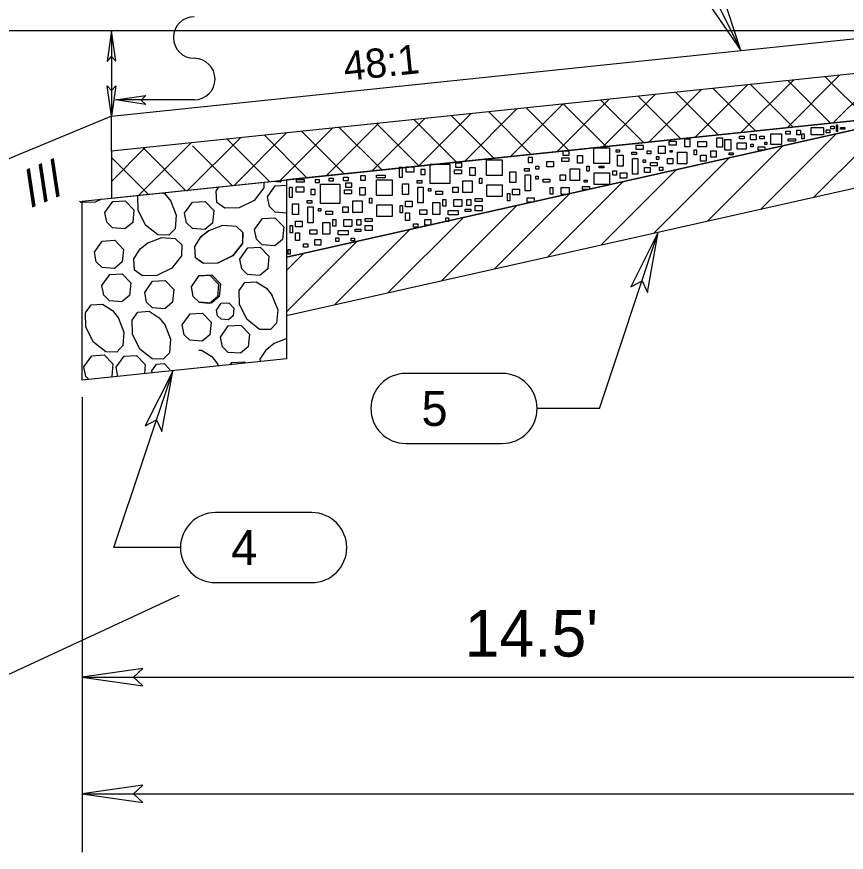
# Model space of a CAD drawing. Extents: x 6561 to 6787, y 19927 to 20919.
# Drawn here: x 6685.44 to 6699.64, y 20854.58 to 20868.89 of the extents above; entities that cross this region are included whole.
import ezdxf

# ---------------------------------------------------------------- set-up
doc = ezdxf.new("R2010")
doc.units = 0
for name, color, linetype in [('Level 1', 7, 'Continuous'), ('Level 10', 7, 'Continuous'), ('Level 3', 7, 'Continuous'), ('Level 4', 7, 'Continuous'), ('Level 5', 7, 'Continuous'), ('Level 7', 7, 'Continuous'), ('Level 8', 7, 'Continuous')]:
    doc.layers.add(name, color=color, linetype=linetype)

msp = doc.modelspace()

# ---------------------------------------------------------------- linework, layer by layer
at = {"layer": 'Level 1'}
for p, q in [((6696.539, 20870.929), (6697.838, 20868.315)), ((6779.047, 20868.65), (6628.473, 20868.65)), ((6687.057, 20868.65), (6687.057, 20867.192)), ((6688.476, 20867.47), (6687.127, 20867.47)), ((6695.417, 20862.184), (6696.424, 20865.206)), ((6687.101, 20859.8), (6688.108, 20862.822)), ((6693.75, 20862.784), (6692.101, 20862.784)), ((6686.557, 20862.377), (6686.557, 20854.582)), ((6695.417, 20862.184), (6694.35, 20862.184)), ((6692.101, 20861.584), (6693.75, 20861.584)), ((6693.75, 20861.584), (6693.75, 20861.584)), ((6690.488, 20860.4), (6688.84, 20860.4)), ((6688.24, 20859.8), (6687.101, 20859.8)), ((6688.84, 20859.2), (6690.488, 20859.2)), ((6690.488, 20859.2), (6690.488, 20859.2)), ((6686.557, 20857.581), (6701.057, 20857.581)), ((6686.557, 20855.581), (6715.557, 20855.581))]:
    msp.add_line(p, q, dxfattribs=at)
for points in [[(6697.838, 20868.315), (6697.514, 20869.313), (6697.45, 20869.103), (6697.245, 20869.18)], [(6687.057, 20868.65), (6686.985, 20868.13), (6687.059, 20868.211), (6687.135, 20868.131)], [(6687.057, 20867.192), (6686.985, 20867.711), (6687.059, 20867.631), (6687.135, 20867.711)], [(6687.127, 20867.47), (6687.647, 20867.542), (6687.566, 20867.467), (6687.646, 20867.392)], [(6696.424, 20865.206), (6695.954, 20864.268), (6696.147, 20864.373), (6696.238, 20864.173)], [(6688.108, 20862.822), (6687.638, 20861.884), (6687.831, 20861.989), (6687.922, 20861.79)], [(6686.557, 20857.581), (6687.596, 20857.432), (6687.436, 20857.581), (6687.596, 20857.731)], [(6686.557, 20855.581), (6687.596, 20855.432), (6687.436, 20855.581), (6687.596, 20855.731)]]:
    msp.add_lwpolyline(points, close=True, dxfattribs=at)
for centre, radius, start, end in [((6688.476, 20868.538), 0.356, 90, 270), ((6688.476, 20867.826), 0.356, 270, 90), ((6692.101, 20862.184), 0.6, 90, 270), ((6693.75, 20862.184), 0.6, 270, 90), ((6688.84, 20859.8), 0.6, 90, 270), ((6690.488, 20859.8), 0.6, 270, 90)]:
    msp.add_arc(centre, radius, start, end, dxfattribs=at)
at = {"layer": 'Level 10'}
for p, q in [((6701.057, 20867.246), (6690.057, 20864.778)), ((6699.091, 20865.805), (6700.381, 20867.094)), ((6698.18, 20865.6), (6699.469, 20866.889)), ((6697.268, 20865.395), (6698.557, 20866.685)), ((6696.356, 20865.191), (6697.646, 20866.48)), ((6695.445, 20864.986), (6696.734, 20866.276)), ((6690.057, 20863.778), (6701.057, 20866.246)), ((6690.057, 20866.1), (6690.057, 20863.033)), ((6694.533, 20864.782), (6695.822, 20866.071)), ((6693.621, 20864.577), (6694.911, 20865.867)), ((6692.71, 20864.373), (6693.999, 20865.662)), ((6691.798, 20864.168), (6693.087, 20865.457)), ((6690.887, 20863.964), (6692.176, 20865.253)), ((6690.057, 20863.841), (6691.264, 20865.048)), ((6690.057, 20864.548), (6690.352, 20864.844)), ((6690.057, 20864.778), (6690.057, 20863.778))]:
    msp.add_line(p, q, dxfattribs=at)
at = {"layer": 'Level 3'}
for p, q in [((6701.057, 20868.05), (6687.057, 20866.592)), ((6699.528, 20867.891), (6698.63, 20866.993)), ((6700.013, 20867.137), (6699.284, 20867.865)), ((6700.318, 20867.973), (6699.42, 20867.075)), ((6697.95, 20867.726), (6697.052, 20866.828)), ((6698.739, 20867.808), (6697.841, 20866.911)), ((6698.732, 20867.003), (6698.004, 20867.732)), ((6699.372, 20867.07), (6698.644, 20867.799)), ((6696.371, 20867.562), (6695.473, 20866.664)), ((6697.16, 20867.644), (6696.262, 20866.746)), ((6697.451, 20866.87), (6696.723, 20867.598)), ((6698.092, 20866.937), (6697.363, 20867.665)), ((6695.582, 20867.48), (6694.684, 20866.582)), ((6696.171, 20866.737), (6695.442, 20867.465)), ((6696.811, 20866.803), (6696.082, 20867.532)), ((6694.003, 20867.315), (6693.105, 20866.417)), ((6694.249, 20866.536), (6693.521, 20867.265)), ((6694.792, 20867.397), (6693.894, 20866.499)), ((6694.89, 20866.603), (6694.161, 20867.332)), ((6695.53, 20866.67), (6694.802, 20867.398)), ((6687.057, 20865.787), (6701.057, 20867.246)), ((6692.424, 20867.151), (6691.526, 20866.253)), ((6692.969, 20866.403), (6692.24, 20867.131)), ((6693.214, 20867.233), (6692.316, 20866.335)), ((6693.609, 20866.47), (6692.88, 20867.198)), ((6690.846, 20866.986), (6689.948, 20866.088)), ((6691.635, 20867.068), (6690.737, 20866.171)), ((6691.688, 20866.27), (6690.959, 20866.998)), ((6692.328, 20866.336), (6691.6, 20867.065)), ((6690.056, 20866.904), (6689.158, 20866.006)), ((6690.407, 20866.136), (6689.678, 20866.865)), ((6691.047, 20866.203), (6690.319, 20866.931)), ((6688.424, 20866.734), (6687.526, 20865.836)), ((6689.267, 20866.822), (6688.352, 20865.907)), ((6689.767, 20866.07), (6689.038, 20866.798)), ((6687.635, 20866.652), (6687.057, 20866.074)), ((6687.057, 20866.592), (6687.057, 20865.787)), ((6688.328, 20865.92), (6687.6, 20866.648)), ((6689.126, 20866.003), (6688.449, 20866.68)), ((6687.688, 20865.853), (6687.057, 20866.484))]:
    msp.add_line(p, q, dxfattribs=at)
at = {"layer": 'Level 4'}
for p, q in [((6701.057, 20867.246), (6690.057, 20866.1)), ((6690.057, 20864.778), (6701.057, 20867.246)), ((6690.057, 20866.1), (6690.057, 20864.778))]:
    msp.add_line(p, q, dxfattribs=at)
for points in [[(6699.252, 20866.869), (6699.04, 20866.869), (6699.04, 20866.994), (6699.252, 20866.994)], [(6699.382, 20867.022), (6699.437, 20867.022), (6699.437, 20866.975), (6699.382, 20866.975)], [(6699.495, 20866.931), (6699.479, 20866.931), (6699.479, 20867.045), (6699.495, 20867.045)], [(6699.547, 20866.998), (6699.617, 20866.998), (6699.617, 20866.971), (6699.547, 20866.971)], [(6697.813, 20866.847), (6697.895, 20866.847), (6697.895, 20866.804), (6697.813, 20866.804)], [(6698.001, 20866.877), (6698.099, 20866.877), (6698.099, 20866.787), (6698.001, 20866.787)], [(6698.237, 20866.802), (6698.166, 20866.802), (6698.166, 20866.85), (6698.237, 20866.85)], [(6698.35, 20866.889), (6698.535, 20866.889), (6698.535, 20866.708), (6698.35, 20866.708)], [(6698.608, 20866.935), (6698.683, 20866.935), (6698.683, 20866.884), (6698.608, 20866.884)], [(6698.797, 20866.951), (6698.859, 20866.951), (6698.859, 20866.869), (6698.797, 20866.869)], [(6698.881, 20866.886), (6698.924, 20866.886), (6698.924, 20866.8), (6698.881, 20866.8)], [(6699.301, 20866.956), (6699.362, 20866.956), (6699.362, 20866.907), (6699.301, 20866.907)], [(6696.732, 20866.695), (6696.61, 20866.695), (6696.61, 20866.761), (6696.732, 20866.761)], [(6696.964, 20866.667), (6696.877, 20866.667), (6696.877, 20866.801), (6696.964, 20866.801)], [(6697.103, 20866.756), (6697.248, 20866.756), (6697.248, 20866.666), (6697.103, 20866.666)], [(6697.429, 20866.819), (6697.527, 20866.819), (6697.527, 20866.658), (6697.429, 20866.658)], [(6697.668, 20866.607), (6697.566, 20866.607), (6697.566, 20866.792), (6697.668, 20866.792)], [(6697.93, 20866.626), (6697.777, 20866.626), (6697.777, 20866.732), (6697.93, 20866.732)], [(6698.009, 20866.714), (6698.048, 20866.714), (6698.048, 20866.666), (6698.009, 20866.666)], [(6698.248, 20866.744), (6698.284, 20866.744), (6698.284, 20866.704), (6698.248, 20866.704)], [(6698.651, 20866.802), (6698.773, 20866.802), (6698.773, 20866.763), (6698.651, 20866.763)], [(6694.9, 20866.593), (6694.79, 20866.593), (6694.79, 20866.522), (6694.9, 20866.522)], [(6695.32, 20866.648), (6695.591, 20866.648), (6695.591, 20866.381), (6695.32, 20866.381)], [(6695.703, 20866.615), (6695.758, 20866.615), (6695.758, 20866.572), (6695.703, 20866.572)], [(6695.97, 20866.577), (6696.053, 20866.577), (6696.053, 20866.534), (6695.97, 20866.534)], [(6696.037, 20866.627), (6696.17, 20866.627), (6696.17, 20866.686), (6696.037, 20866.686)], [(6696.296, 20866.545), (6696.233, 20866.545), (6696.233, 20866.596), (6696.296, 20866.596)], [(6696.429, 20866.678), (6696.543, 20866.678), (6696.543, 20866.552), (6696.429, 20866.552)], [(6696.628, 20866.603), (6696.663, 20866.603), (6696.663, 20866.575), (6696.628, 20866.575)], [(6696.755, 20866.573), (6696.916, 20866.573), (6696.916, 20866.372), (6696.755, 20866.372)], [(6697.038, 20866.616), (6697.081, 20866.616), (6697.081, 20866.53), (6697.038, 20866.53)], [(6697.417, 20866.489), (6697.323, 20866.489), (6697.323, 20866.595), (6697.417, 20866.595)], [(6697.637, 20866.564), (6697.708, 20866.564), (6697.708, 20866.528), (6697.637, 20866.528)], [(6698.249, 20866.611), (6698.135, 20866.611), (6698.135, 20866.666), (6698.249, 20866.666)], [(6693.482, 20866.441), (6693.753, 20866.441), (6693.753, 20866.173), (6693.482, 20866.173)], [(6694.197, 20866.397), (6694.272, 20866.397), (6694.272, 20866.483), (6694.197, 20866.483)], [(6694.517, 20866.415), (6694.631, 20866.415), (6694.631, 20866.325), (6694.517, 20866.325)], [(6694.892, 20866.412), (6694.771, 20866.412), (6694.771, 20866.479), (6694.892, 20866.479)], [(6695.124, 20866.385), (6695.038, 20866.385), (6695.038, 20866.518), (6695.124, 20866.518)], [(6695.825, 20866.337), (6695.723, 20866.337), (6695.723, 20866.522), (6695.825, 20866.522)], [(6695.982, 20866.467), (6696.076, 20866.467), (6696.076, 20866.196), (6695.982, 20866.196)], [(6696.167, 20866.443), (6696.206, 20866.443), (6696.206, 20866.396), (6696.167, 20866.396)], [(6696.386, 20866.454), (6696.437, 20866.454), (6696.437, 20866.497), (6696.386, 20866.497)], [(6696.673, 20866.372), (6696.583, 20866.372), (6696.583, 20866.467), (6696.673, 20866.467)], [(6697.244, 20866.422), (6697.15, 20866.422), (6697.15, 20866.524), (6697.244, 20866.524)], [(6692.045, 20866.311), (6691.986, 20866.311), (6691.986, 20866.146), (6692.045, 20866.146)], [(6692.104, 20866.323), (6692.238, 20866.323), (6692.238, 20866.229), (6692.104, 20866.229)], [(6692.359, 20866.189), (6692.434, 20866.189), (6692.434, 20866.276), (6692.359, 20866.276)], [(6692.52, 20866.37), (6692.854, 20866.37), (6692.854, 20866.036), (6692.52, 20866.036)], [(6693.054, 20866.205), (6692.933, 20866.205), (6692.933, 20866.272), (6693.054, 20866.272)], [(6693.062, 20866.386), (6692.952, 20866.386), (6692.952, 20866.315), (6693.062, 20866.315)], [(6693.286, 20866.177), (6693.199, 20866.177), (6693.199, 20866.311), (6693.286, 20866.311)], [(6694.131, 20866.294), (6694.213, 20866.294), (6694.213, 20866.251), (6694.131, 20866.251)], [(6694.325, 20866.336), (6694.376, 20866.336), (6694.376, 20866.285), (6694.325, 20866.285)], [(6694.916, 20866.291), (6695.077, 20866.291), (6695.077, 20866.09), (6694.916, 20866.09)], [(6695.199, 20866.334), (6695.242, 20866.334), (6695.242, 20866.247), (6695.199, 20866.247)], [(6695.491, 20866.305), (6695.409, 20866.305), (6695.409, 20866.336), (6695.491, 20866.336)], [(6696.186, 20866.309), (6696.284, 20866.309), (6696.284, 20866.226), (6696.186, 20866.226)], [(6696.406, 20866.341), (6696.292, 20866.341), (6696.292, 20866.396), (6696.406, 20866.396)], [(6696.443, 20866.316), (6696.502, 20866.316), (6696.502, 20866.261), (6696.443, 20866.261)], [(6690.785, 20866.126), (6690.856, 20866.126), (6690.856, 20866.079), (6690.785, 20866.079)], [(6691.032, 20866.146), (6691.115, 20866.146), (6691.115, 20866.083), (6691.032, 20866.083)], [(6691.327, 20866.177), (6691.401, 20866.177), (6691.401, 20866.091), (6691.327, 20866.091)], [(6691.598, 20866.181), (6691.747, 20866.181), (6691.747, 20866.134), (6691.598, 20866.134)], [(6693.36, 20866.126), (6693.404, 20866.126), (6693.404, 20866.04), (6693.36, 20866.04)], [(6693.985, 20866.055), (6693.883, 20866.055), (6693.883, 20866.239), (6693.985, 20866.239)], [(6694.142, 20866.184), (6694.237, 20866.184), (6694.237, 20865.913), (6694.142, 20865.913)], [(6694.327, 20866.161), (6694.366, 20866.161), (6694.366, 20866.114), (6694.327, 20866.114)], [(6694.833, 20866.09), (6694.743, 20866.09), (6694.743, 20866.184), (6694.833, 20866.184)], [(6695.591, 20866.019), (6695.324, 20866.019), (6695.324, 20866.22), (6695.591, 20866.22)], [(6695.644, 20866.254), (6695.711, 20866.254), (6695.711, 20866.179), (6695.644, 20866.179)], [(6695.888, 20866.129), (6695.77, 20866.129), (6695.77, 20866.223), (6695.888, 20866.223)], [(6690.22, 20865.981), (6690.353, 20865.981), (6690.353, 20865.887), (6690.22, 20865.887)], [(6690.357, 20866.06), (6690.227, 20866.06), (6690.227, 20866.107), (6690.357, 20866.107)], [(6690.549, 20866.052), (6690.624, 20866.052), (6690.624, 20866.099), (6690.549, 20866.099)], [(6690.636, 20866.028), (6690.969, 20866.028), (6690.969, 20865.694), (6690.636, 20865.694)], [(6691.178, 20866.044), (6691.068, 20866.044), (6691.068, 20865.973), (6691.178, 20865.973)], [(6691.598, 20866.099), (6691.869, 20866.099), (6691.869, 20865.832), (6691.598, 20865.832)], [(6692.147, 20865.847), (6692.045, 20865.847), (6692.045, 20866.032), (6692.147, 20866.032)], [(6692.293, 20866.087), (6692.375, 20866.087), (6692.375, 20866.044), (6692.293, 20866.044)], [(6692.304, 20865.977), (6692.399, 20865.977), (6692.399, 20865.706), (6692.304, 20865.706)], [(6692.995, 20865.883), (6692.905, 20865.883), (6692.905, 20865.977), (6692.995, 20865.977)], [(6693.078, 20866.083), (6693.239, 20866.083), (6693.239, 20865.883), (6693.078, 20865.883)], [(6693.753, 20865.812), (6693.486, 20865.812), (6693.486, 20866.012), (6693.753, 20866.012)], [(6694.566, 20866.059), (6694.453, 20866.059), (6694.453, 20866.114), (6694.566, 20866.114)], [(6695.128, 20865.988), (6695.246, 20865.988), (6695.246, 20865.937), (6695.128, 20865.937)], [(6695.153, 20866.097), (6695.204, 20866.097), (6695.204, 20866.061), (6695.153, 20866.061)], [(6690.161, 20865.969), (6690.102, 20865.969), (6690.102, 20865.804), (6690.161, 20865.804)], [(6690.475, 20865.847), (6690.549, 20865.847), (6690.549, 20865.934), (6690.475, 20865.934)], [(6691.17, 20865.863), (6691.048, 20865.863), (6691.048, 20865.93), (6691.17, 20865.93)], [(6691.401, 20865.836), (6691.315, 20865.836), (6691.315, 20865.969), (6691.401, 20865.969)], [(6692.489, 20865.953), (6692.528, 20865.953), (6692.528, 20865.906), (6692.489, 20865.906)], [(6692.728, 20865.851), (6692.615, 20865.851), (6692.615, 20865.906), (6692.728, 20865.906)], [(6693.84, 20865.866), (6693.883, 20865.866), (6693.883, 20865.74), (6693.84, 20865.74)], [(6694.048, 20865.846), (6693.93, 20865.846), (6693.93, 20865.941), (6694.048, 20865.941)], [(6694.621, 20865.854), (6694.574, 20865.854), (6694.574, 20865.968), (6694.621, 20865.968)], [(6694.763, 20865.968), (6694.9, 20865.968), (6694.9, 20865.85), (6694.763, 20865.85)], [(6690.263, 20865.505), (6690.161, 20865.505), (6690.161, 20865.69), (6690.263, 20865.69)], [(6690.408, 20865.745), (6690.491, 20865.745), (6690.491, 20865.702), (6690.408, 20865.702)], [(6691.193, 20865.741), (6691.354, 20865.741), (6691.354, 20865.541), (6691.193, 20865.541)], [(6691.476, 20865.784), (6691.519, 20865.784), (6691.519, 20865.698), (6691.476, 20865.698)], [(6692.21, 20865.639), (6692.092, 20865.639), (6692.092, 20865.733), (6692.21, 20865.733)], [(6692.563, 20865.71), (6692.685, 20865.71), (6692.685, 20865.509), (6692.563, 20865.509)], [(6692.783, 20865.647), (6692.736, 20865.647), (6692.736, 20865.761), (6692.783, 20865.761)], [(6692.925, 20865.761), (6693.062, 20865.761), (6693.062, 20865.643), (6692.925, 20865.643)], [(6693.145, 20865.765), (6693.211, 20865.765), (6693.211, 20865.663), (6693.145, 20865.663)], [(6693.29, 20865.781), (6693.408, 20865.781), (6693.408, 20865.729), (6693.29, 20865.729)], [(6694.299, 20865.717), (6694.178, 20865.717), (6694.178, 20865.791), (6694.299, 20865.791)], [(6690.42, 20865.635), (6690.514, 20865.635), (6690.514, 20865.364), (6690.42, 20865.364)], [(6690.604, 20865.612), (6690.644, 20865.612), (6690.644, 20865.564), (6690.604, 20865.564)], [(6690.844, 20865.509), (6690.73, 20865.509), (6690.73, 20865.564), (6690.844, 20865.564)], [(6691.111, 20865.541), (6691.021, 20865.541), (6691.021, 20865.635), (6691.111, 20865.635)], [(6691.869, 20865.47), (6691.602, 20865.47), (6691.602, 20865.67), (6691.869, 20865.67)], [(6692.002, 20865.659), (6692.045, 20865.659), (6692.045, 20865.533), (6692.002, 20865.533)], [(6692.461, 20865.509), (6692.34, 20865.509), (6692.34, 20865.584), (6692.461, 20865.584)], [(6692.995, 20865.498), (6692.827, 20865.498), (6692.827, 20865.576), (6692.995, 20865.576)], [(6693.211, 20865.556), (6693.117, 20865.556), (6693.117, 20865.6), (6693.211, 20865.6)], [(6693.408, 20865.572), (6693.286, 20865.572), (6693.286, 20865.659), (6693.408, 20865.659)], [(6690.899, 20865.305), (6690.852, 20865.305), (6690.852, 20865.419), (6690.899, 20865.419)], [(6691.04, 20865.419), (6691.178, 20865.419), (6691.178, 20865.301), (6691.04, 20865.301)], [(6691.26, 20865.423), (6691.327, 20865.423), (6691.327, 20865.321), (6691.26, 20865.321)], [(6691.405, 20865.439), (6691.523, 20865.439), (6691.523, 20865.388), (6691.405, 20865.388)], [(6692.092, 20865.533), (6692.163, 20865.533), (6692.163, 20865.403), (6692.092, 20865.403)], [(6692.426, 20865.423), (6692.528, 20865.423), (6692.528, 20865.325), (6692.426, 20865.325)], [(6692.834, 20865.388), (6692.783, 20865.388), (6692.783, 20865.45), (6692.834, 20865.45)], [(6690.118, 20865.317), (6690.161, 20865.317), (6690.161, 20865.191), (6690.118, 20865.191)], [(6690.326, 20865.297), (6690.208, 20865.297), (6690.208, 20865.391), (6690.326, 20865.391)], [(6690.679, 20865.368), (6690.801, 20865.368), (6690.801, 20865.167), (6690.679, 20865.167)], [(6691.523, 20865.23), (6691.401, 20865.23), (6691.401, 20865.317), (6691.523, 20865.317)], [(6692.23, 20865.344), (6692.304, 20865.344), (6692.304, 20865.289), (6692.23, 20865.289)], [(6690.208, 20865.191), (6690.279, 20865.191), (6690.279, 20865.061), (6690.208, 20865.061)], [(6690.577, 20865.167), (6690.455, 20865.167), (6690.455, 20865.242), (6690.577, 20865.242)], [(6691.111, 20865.156), (6690.942, 20865.156), (6690.942, 20865.234), (6691.111, 20865.234)], [(6691.327, 20865.215), (6691.233, 20865.215), (6691.233, 20865.258), (6691.327, 20865.258)], [(6690.345, 20865.002), (6690.42, 20865.002), (6690.42, 20864.947), (6690.345, 20864.947)], [(6690.542, 20865.081), (6690.644, 20865.081), (6690.644, 20864.983), (6690.542, 20864.983)], [(6690.95, 20865.046), (6690.899, 20865.046), (6690.899, 20865.108), (6690.95, 20865.108)], [(6691.166, 20865.101), (6691.221, 20865.101), (6691.221, 20865.053), (6691.166, 20865.053)], [(6690.125, 20864.904), (6690.078, 20864.904), (6690.078, 20864.833), (6690.125, 20864.833)]]:
    msp.add_lwpolyline(points, close=True, dxfattribs=at)
at = {"layer": 'Level 5'}
for p, q in [((6686.557, 20865.735), (6690.057, 20866.1)), ((6690.057, 20866.1), (6690.057, 20863.033)), ((6686.557, 20862.669), (6686.557, 20865.735)), ((6690.057, 20863.033), (6686.557, 20862.669))]:
    msp.add_line(p, q, dxfattribs=at)
for points in [[(6689.67, 20866.059), (6689.668, 20865.962), (6689.501, 20865.749), (6689.244, 20865.62), (6689.001, 20865.616), (6688.864, 20865.713), (6688.852, 20865.906), (6688.898, 20865.979)], [(6689.731, 20865.808), (6689.865, 20866), (6690.057, 20866.011)], [(6689.983, 20866.092), (6689.946, 20866.062), (6689.819, 20866.071), (6689.815, 20866.075)], [(6688.068, 20865.745), (6688.167, 20865.493), (6688.147, 20865.262), (6688.043, 20865.152), (6687.855, 20865.156), (6687.642, 20865.322), (6687.514, 20865.58), (6687.509, 20865.823), (6687.518, 20865.835)], [(6687.944, 20865.88), (6687.973, 20865.862), (6688.074, 20865.735)], [(6686.889, 20865.77), (6686.781, 20865.716), (6686.538, 20865.712), (6686.512, 20865.73)], [(6686.946, 20865.54), (6687.08, 20865.731), (6687.295, 20865.743), (6687.444, 20865.589), (6687.423, 20865.372), (6687.29, 20865.261), (6687.078, 20865.277), (6686.978, 20865.374), (6686.946, 20865.54)], [(6688.312, 20865.527), (6688.446, 20865.718), (6688.661, 20865.73), (6688.81, 20865.576), (6688.789, 20865.359), (6688.656, 20865.249), (6688.444, 20865.264), (6688.344, 20865.361), (6688.312, 20865.527)], [(6690.057, 20865.531), (6689.863, 20865.545), (6689.763, 20865.642), (6689.731, 20865.808)], [(6689.51, 20865.248), (6689.645, 20865.44), (6689.859, 20865.452), (6690.008, 20865.297), (6689.987, 20865.08), (6689.854, 20864.97), (6689.642, 20864.985), (6689.543, 20865.082), (6689.51, 20865.248)], [(6688.712, 20865.226), (6688.964, 20865.326), (6689.195, 20865.306), (6689.305, 20865.202), (6689.301, 20865.014), (6689.134, 20864.801), (6688.877, 20864.672), (6688.634, 20864.668), (6688.498, 20864.765), (6688.485, 20864.959), (6688.595, 20865.131), (6688.722, 20865.233)], [(6688.713, 20865.224), (6688.965, 20865.323), (6689.196, 20865.304), (6689.306, 20865.199), (6689.302, 20865.012), (6689.136, 20864.799), (6688.878, 20864.67), (6688.635, 20864.666), (6688.557, 20864.721)], [(6688.557, 20865.067), (6688.597, 20865.129), (6688.724, 20865.23)], [(6686.767, 20864.861), (6686.901, 20865.052), (6687.116, 20865.064), (6687.265, 20864.909), (6687.243, 20864.693), (6687.111, 20864.582), (6686.899, 20864.598), (6686.799, 20864.694), (6686.767, 20864.861)], [(6687.669, 20865.014), (6687.92, 20865.113), (6688.151, 20865.093), (6688.261, 20864.989), (6688.258, 20864.801), (6688.091, 20864.588), (6687.833, 20864.46), (6687.591, 20864.455), (6687.454, 20864.552), (6687.441, 20864.746), (6687.552, 20864.919), (6687.679, 20865.02)], [(6689.257, 20864.742), (6689.392, 20864.934), (6689.606, 20864.946), (6689.755, 20864.791), (6689.734, 20864.574), (6689.601, 20864.464), (6689.389, 20864.479), (6689.29, 20864.576), (6689.257, 20864.742)], [(6686.893, 20864.288), (6687.028, 20864.479), (6687.242, 20864.492), (6687.391, 20864.337), (6687.37, 20864.12), (6687.237, 20864.01), (6687.025, 20864.025), (6686.926, 20864.122), (6686.893, 20864.288)], [(6688.427, 20864.268), (6688.561, 20864.459), (6688.776, 20864.471), (6688.925, 20864.317), (6688.904, 20864.1), (6688.771, 20863.99), (6688.559, 20864.005), (6688.459, 20864.102), (6688.427, 20864.268)], [(6688.557, 20864.455), (6688.744, 20864.466), (6688.893, 20864.311), (6688.872, 20864.094), (6688.739, 20863.984), (6688.557, 20863.997)], [(6687.628, 20864.171), (6687.763, 20864.362), (6687.977, 20864.374), (6688.127, 20864.22), (6688.105, 20864.003), (6687.972, 20863.893), (6687.76, 20863.908), (6687.661, 20864.005), (6687.628, 20864.171)], [(6689.806, 20864.127), (6689.906, 20863.876), (6689.886, 20863.645), (6689.782, 20863.535), (6689.594, 20863.538), (6689.381, 20863.705), (6689.252, 20863.963), (6689.248, 20864.205), (6689.345, 20864.342), (6689.539, 20864.355), (6689.712, 20864.244), (6689.813, 20864.117)], [(6688.857, 20863.87), (6688.938, 20863.985), (6689.066, 20863.993), (6689.156, 20863.9), (6689.143, 20863.77), (6689.063, 20863.703), (6688.936, 20863.713), (6688.876, 20863.771), (6688.857, 20863.87)], [(6687.173, 20863.743), (6687.273, 20863.492), (6687.253, 20863.261), (6687.148, 20863.151), (6686.961, 20863.154), (6686.748, 20863.321), (6686.619, 20863.579), (6686.615, 20863.821), (6686.712, 20863.958), (6686.905, 20863.971), (6687.078, 20863.86), (6687.179, 20863.733)], [(6687.97, 20863.621), (6688.07, 20863.37), (6688.05, 20863.139), (6687.945, 20863.029), (6687.758, 20863.032), (6687.545, 20863.199), (6687.416, 20863.457), (6687.412, 20863.699), (6687.509, 20863.836), (6687.702, 20863.849), (6687.875, 20863.738), (6687.976, 20863.611)], [(6688.27, 20863.614), (6688.404, 20863.805), (6688.619, 20863.817), (6688.768, 20863.663), (6688.746, 20863.446), (6688.614, 20863.336), (6688.402, 20863.351), (6688.302, 20863.448), (6688.27, 20863.614)], [(6688.925, 20863.408), (6689.06, 20863.6), (6689.275, 20863.612), (6689.424, 20863.457), (6689.402, 20863.24), (6689.27, 20863.13), (6689.058, 20863.145), (6688.958, 20863.242), (6688.926, 20863.408)], [(6689.611, 20862.987), (6689.608, 20863.028), (6689.719, 20863.201), (6689.846, 20863.302)], [(6689.836, 20863.296), (6690.057, 20863.384)], [(6688.557, 20863.181), (6688.603, 20863.184), (6688.776, 20863.073), (6688.877, 20862.946)], [(6686.586, 20862.897), (6686.72, 20863.088), (6686.935, 20863.1), (6687.084, 20862.946), (6687.063, 20862.729), (6687.052, 20862.72)], [(6687.139, 20862.889), (6687.274, 20863.08), (6687.488, 20863.092), (6687.637, 20862.938), (6687.622, 20862.78)], [(6689.093, 20862.933), (6689.12, 20862.97), (6689.334, 20862.983), (6689.356, 20862.96)], [(6686.67, 20862.68), (6686.618, 20862.731), (6686.586, 20862.897)], [(6687.17, 20862.732), (6687.139, 20862.889)], [(6687.751, 20862.83), (6687.832, 20862.944), (6687.96, 20862.952), (6688.05, 20862.859), (6688.046, 20862.824)], [(6687.758, 20862.794), (6687.751, 20862.83)], [(6688.871, 20862.956), (6688.889, 20862.912)]]:
    msp.add_lwpolyline(points, dxfattribs=at)
at = {"layer": 'Level 7'}
for p, q in [((6687.057, 20867.192), (6679.057, 20863.858)), ((6683.125, 20856.629), (6688.218, 20858.984))]:
    msp.add_line(p, q, dxfattribs=at)
at = {"layer": 'Level 8'}
for p, q in [((6687.057, 20867.192), (6701.057, 20868.65)), ((6701.057, 20868.05), (6687.057, 20866.592)), ((6687.057, 20866.592), (6687.057, 20867.192))]:
    msp.add_line(p, q, dxfattribs=at)

# ---------------------------------------------------------------- texts
at = {"layer": 'Level 1'}
msp.add_text('48:1', height=0.5, rotation=5.9469, dxfattribs=at).set_placement((6691.059, 20867.794))
for s, height, p in [(' 5', 0.6, (6692.147, 20861.884)), (' 4', 0.6, (6688.886, 20859.5)), ("14.5'", 0.8, (6693.108, 20857.934))]:
    msp.add_text(s, height=height, dxfattribs=at).set_placement(p)
at = {"layer": 'Level 7'}
msp.add_text('///', height=0.6, rotation=22.6195, dxfattribs=at).set_placement((6685.698, 20865.633))

doc.saveas('drawing.dxf')
